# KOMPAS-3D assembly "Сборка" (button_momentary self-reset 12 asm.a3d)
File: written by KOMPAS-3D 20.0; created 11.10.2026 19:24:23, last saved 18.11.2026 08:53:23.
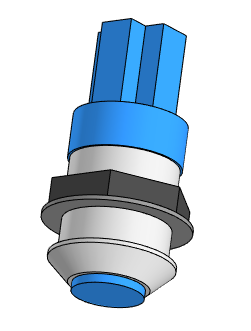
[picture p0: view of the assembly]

Document properties: Полное имя файла: D:\RicWork\Project-EPS32\box_compas\переключатели и кнопки\button_momentary self-reset 12 asm.a3d

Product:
- Part/product: Сборка
    Масса: 0.023656
  - Component [detail]: Деталь  | Масса: 0.0186011; source file: button_momentary self-reset 12.m3d
  - Component [detail]: Деталь  | Масса: 0.00505493; source file: button_momentary self-reset 12 up.m3d

Referenced files in D:\RicWork\Project-EPS32\box_compas\переключатели и кнопки\: button_momentary self-reset 12.m3d, button_momentary self-reset 12 up.m3d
